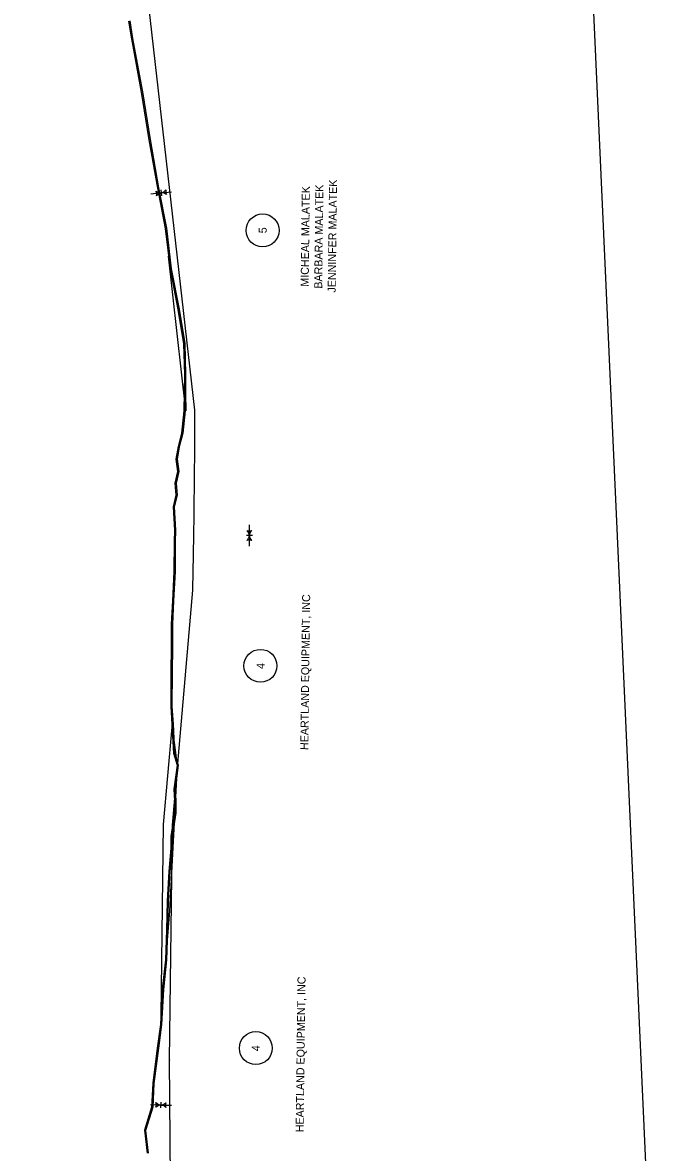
# Model space of a CAD drawing. Extents: x 20504422 to 20508365, y 7965199 to 7983597.
# Drawn here: x 20506611 to 20507690, y 7972142 to 7974062 of the extents above; entities that cross this region are included whole.
import ezdxf

# ---------------------------------------------------------------- set-up
doc = ezdxf.new("R2010")
doc.units = 0
for name, color, linetype in [('SurControl', 7, 'Continuous'), ('SurDikeDam', 7, 'Continuous'), ('SurLotCorner', 7, 'Continuous'), ('SurRipRap', 7, 'Continuous'), ('SurTopOfWater', 7, 'Continuous'), ('SurTreeLineRight', 7, 'Continuous'), ('SurWetlands', 7, 'Continuous')]:
    doc.layers.add(name, color=color, linetype=linetype)

msp = doc.modelspace()

# ---------------------------------------------------------------- linework, layer by layer
at = {"layer": 'SurControl'}
for centre in [(20507018.9, 7973708.7), (20507015.2, 7972968.7), (20507007.3, 7972319)]:
    msp.add_circle(centre, 28, dxfattribs=at)
at = {"layer": 'SurDikeDam'}
for points in [[(20506888.5, 7973402.2), (20506858.7, 7973665), (20506885.8, 7973515.7)], [(20506846.4, 7972374.5), (20506850.4, 7972699), (20506864.9, 7972864.3), (20506873.8, 7972799.1), (20506860.7, 7972552.3)]]:
    msp.add_lwpolyline(points, close=True, dxfattribs=at)
at = {"layer": 'SurLotCorner'}
for p, q in [((20506846.5, 7973772.4), (20506828.7, 7973770.4)), ((20506845.9, 7973777.5), (20506847, 7973767.4)), ((20506846.5, 7973772.4), (20506864.2, 7973774.4)), ((20506996.3, 7973190.1), (20506996.5, 7973208)), ((20507001.4, 7973190), (20506991.2, 7973190.1)), ((20506996.3, 7973190.1), (20506996.1, 7973172.2)), ((20506846, 7972222.3), (20506828.2, 7972222.6)), ((20506846, 7972217.3), (20506846.1, 7972227.4)), ((20506846, 7972222.3), (20506863.9, 7972222.1))]:
    msp.add_line(p, q, dxfattribs=at)
for centre, radius, start, end in [((20506846.4, 7973787), 14.6, 232.5618, 270.369), ((20506827.4, 7973770.3), 11.4, 345.8681, 27.0817), ((20506849.6, 7973758.2), 14.6, 102.5807, 140.388), ((20506843.3, 7973786.7), 14.6, 282.5807, 320.388), ((20506846.6, 7973757.8), 14.6, 52.5618, 90.369), ((20506865.5, 7973774.6), 11.4, 165.8681, 207.0817), ((20506981.8, 7973191.8), 14.6, 315.366, 353.1732), ((20506981.8, 7973188.7), 14.6, 5.3849, 43.1922), ((20506996.5, 7973209.3), 11.4, 248.6722, 289.8859), ((20507010.8, 7973188.3), 14.6, 135.366, 173.1732), ((20507010.8, 7973191.4), 14.6, 185.3849, 223.1922), ((20506996.1, 7973170.9), 11.4, 68.6722, 109.8859), ((20506826.8, 7972222.6), 11.4, 338.6722, 19.8859), ((20506847.4, 7972207.8), 14.6, 95.3849, 133.1922), ((20506847.8, 7972236.8), 14.6, 225.366, 263.1732), ((20506844.7, 7972236.9), 14.6, 275.3849, 313.1922), ((20506844.3, 7972207.8), 14.6, 45.366, 83.1732), ((20506865.2, 7972222.1), 11.4, 158.6722, 199.8859)]:
    msp.add_arc(centre, radius, start, end, dxfattribs=at)
at = {"layer": 'SurRipRap'}
msp.add_lwpolyline([(20505692.1, 7971595), (20507690.1, 7971685.2), (20507549.3, 7974806.4), (20505551.3, 7974716.3)], close=True, dxfattribs=at)
at = {"layer": 'SurTopOfWater'}
for points in [[(20506791, 7974064.3), (20506795.7, 7974034.3), (20506812.4, 7973943.6), (20506825.5, 7973862.6), (20506839.9, 7973780.5), (20506853.3, 7973711.9), (20506861.6, 7973643), (20506874.9, 7973574.2), (20506884.5, 7973516), (20506886, 7973464), (20506885.1, 7973401.9), (20506881.1, 7973364.3), (20506875.1, 7973341.2), (20506871.3, 7973319.8), (20506874.2, 7973299.1), (20506869.5, 7973279), (20506871.4, 7973258.9), (20506866.7, 7973238.9), (20506868.9, 7973199.4), (20506868.4, 7973179.2), (20506868.1, 7973129.2), (20506865.5, 7973079.1), (20506863.6, 7973039.2), (20506863.6, 7972999.3), (20506862.8, 7972959.3), (20506862.6, 7972899.5), (20506864.6, 7972869.6), (20506867.1, 7972820.2), (20506873.5, 7972799.6), (20506868.1, 7972759.1), (20506869.2, 7972739.4), (20506869.2, 7972718.9), (20506863, 7972678.9), (20506862.9, 7972659.1), (20506859.2, 7972619), (20506856.3, 7972569.2), (20506855.4, 7972519.3), (20506853.6, 7972469.1), (20506848.3, 7972419.1), (20506845.1, 7972359.1), (20506839.8, 7972318.9), (20506832.1, 7972259.3), (20506830.2, 7972218.8), (20506817.9, 7972179.4), (20506822.4, 7972140.4)], [(20506793, 7974064.5), (20506797.7, 7974034.6), (20506814.4, 7973944), (20506827.4, 7973863), (20506841.9, 7973780.8), (20506855.2, 7973712.2), (20506863.6, 7973643.3), (20506876.8, 7973574.6), (20506886.5, 7973516.2), (20506888, 7973464.1), (20506887.1, 7973401.8), (20506883.1, 7973364), (20506877.1, 7973340.8), (20506873.3, 7973319.8), (20506876.2, 7973299), (20506871.6, 7973278.8), (20506873.4, 7973258.8), (20506868.7, 7973238.7), (20506870.9, 7973199.4), (20506870.4, 7973179.2), (20506870.1, 7973129.1), (20506867.5, 7973079), (20506865.6, 7973039.2), (20506865.6, 7972999.3), (20506864.8, 7972959.3), (20506864.6, 7972899.6), (20506866.6, 7972869.7), (20506869.1, 7972820.5), (20506875.5, 7972799.8), (20506870.1, 7972759), (20506871.2, 7972739.5), (20506871.2, 7972718.7), (20506865, 7972678.8), (20506864.9, 7972659), (20506861.2, 7972618.8), (20506858.3, 7972569.1), (20506857.4, 7972519.2), (20506855.6, 7972468.9), (20506850.3, 7972418.9), (20506847.1, 7972358.9), (20506841.8, 7972318.7), (20506834.1, 7972259.1), (20506832.2, 7972218.5), (20506820, 7972179.2), (20506824.3, 7972140.7)]]:
    msp.add_lwpolyline(points, dxfattribs=at)
at = {"layer": 'SurTreeLineRight'}
for points in [[(20506903.5, 7973403.1), (20506806.8, 7974255.2), (20506806.9, 7974253.5), (20506807.3, 7974517.6), (20506806.4, 7974522.6), (20506410.1, 7975661.4), (20506409.8, 7975662.3), (20506326.3, 7975860.1), (20506276.5, 7975978.2), (20506277.4, 7975975.4), (20506236.5, 7976175.1), (20506235.6, 7976177.9), (20506157.9, 7976362.2), (20506155.1, 7976366.6), (20506077.1, 7976450.7)], [(20506865, 7971735.1), (20506864.9, 7971756.5), (20506864.9, 7971756.6), (20506860.4, 7972299.1), (20506860.4, 7972298.8), (20506865.4, 7972698.8), (20506865.4, 7972697.7), (20506900.4, 7973097.3), (20506900.4, 7973098.4), (20506901.2, 7973158.1), (20506901.2, 7973158), (20506901.8, 7973191.1), (20506901.8, 7973191.2), (20506902.2, 7973224.2), (20506903.1, 7973295.5)]]:
    msp.add_lwpolyline(points, dxfattribs=at)
msp.add_arc((20500978.6, 7973370.4), 5925, 359.27599, 0.31677, dxfattribs=at)
at = {"layer": 'SurWetlands'}
for p, q in [((20506858.7, 7973665), (20506885.8, 7973515.7)), ((20506885.8, 7973515.7), (20506888.5, 7973402.2)), ((20506864.9, 7972864.3), (20506873.8, 7972799.1)), ((20506873.8, 7972799.1), (20506860.7, 7972552.3)), ((20506860.7, 7972552.3), (20506846.4, 7972374.5))]:
    msp.add_line(p, q, dxfattribs=at)

# ---------------------------------------------------------------- texts
at = {"layer": 'SurControl'}
for s, p in [('BARBARA MALATEK', (20507120.1, 7973609.5)), ('JENNINFER MALATEK', (20507143.1, 7973602.9)), ('MICHEAL MALATEK ', (20507097.1, 7973612.9)), ('5', (20507025.7, 7973703.7)), ('HEARTLAND EQUIPMENT, INC', (20507096.5, 7972825.5)), ('4', (20507022, 7972963.4)), ('HEARTLAND EQUIPMENT, INC', (20507088.6, 7972175.9)), ('4', (20507014, 7972313.7))]:
    msp.add_text(s, height=13.6, rotation=89.2974, dxfattribs=at).set_placement(p)

doc.saveas('drawing.dxf')
